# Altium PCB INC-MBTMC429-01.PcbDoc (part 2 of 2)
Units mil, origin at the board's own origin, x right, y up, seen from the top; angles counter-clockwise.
Board outline 6000 x 4000 mil, 2 copper layers (Top Layer, Bottom Layer); 198 components, 197 nets, 672 pads, 128 vias.
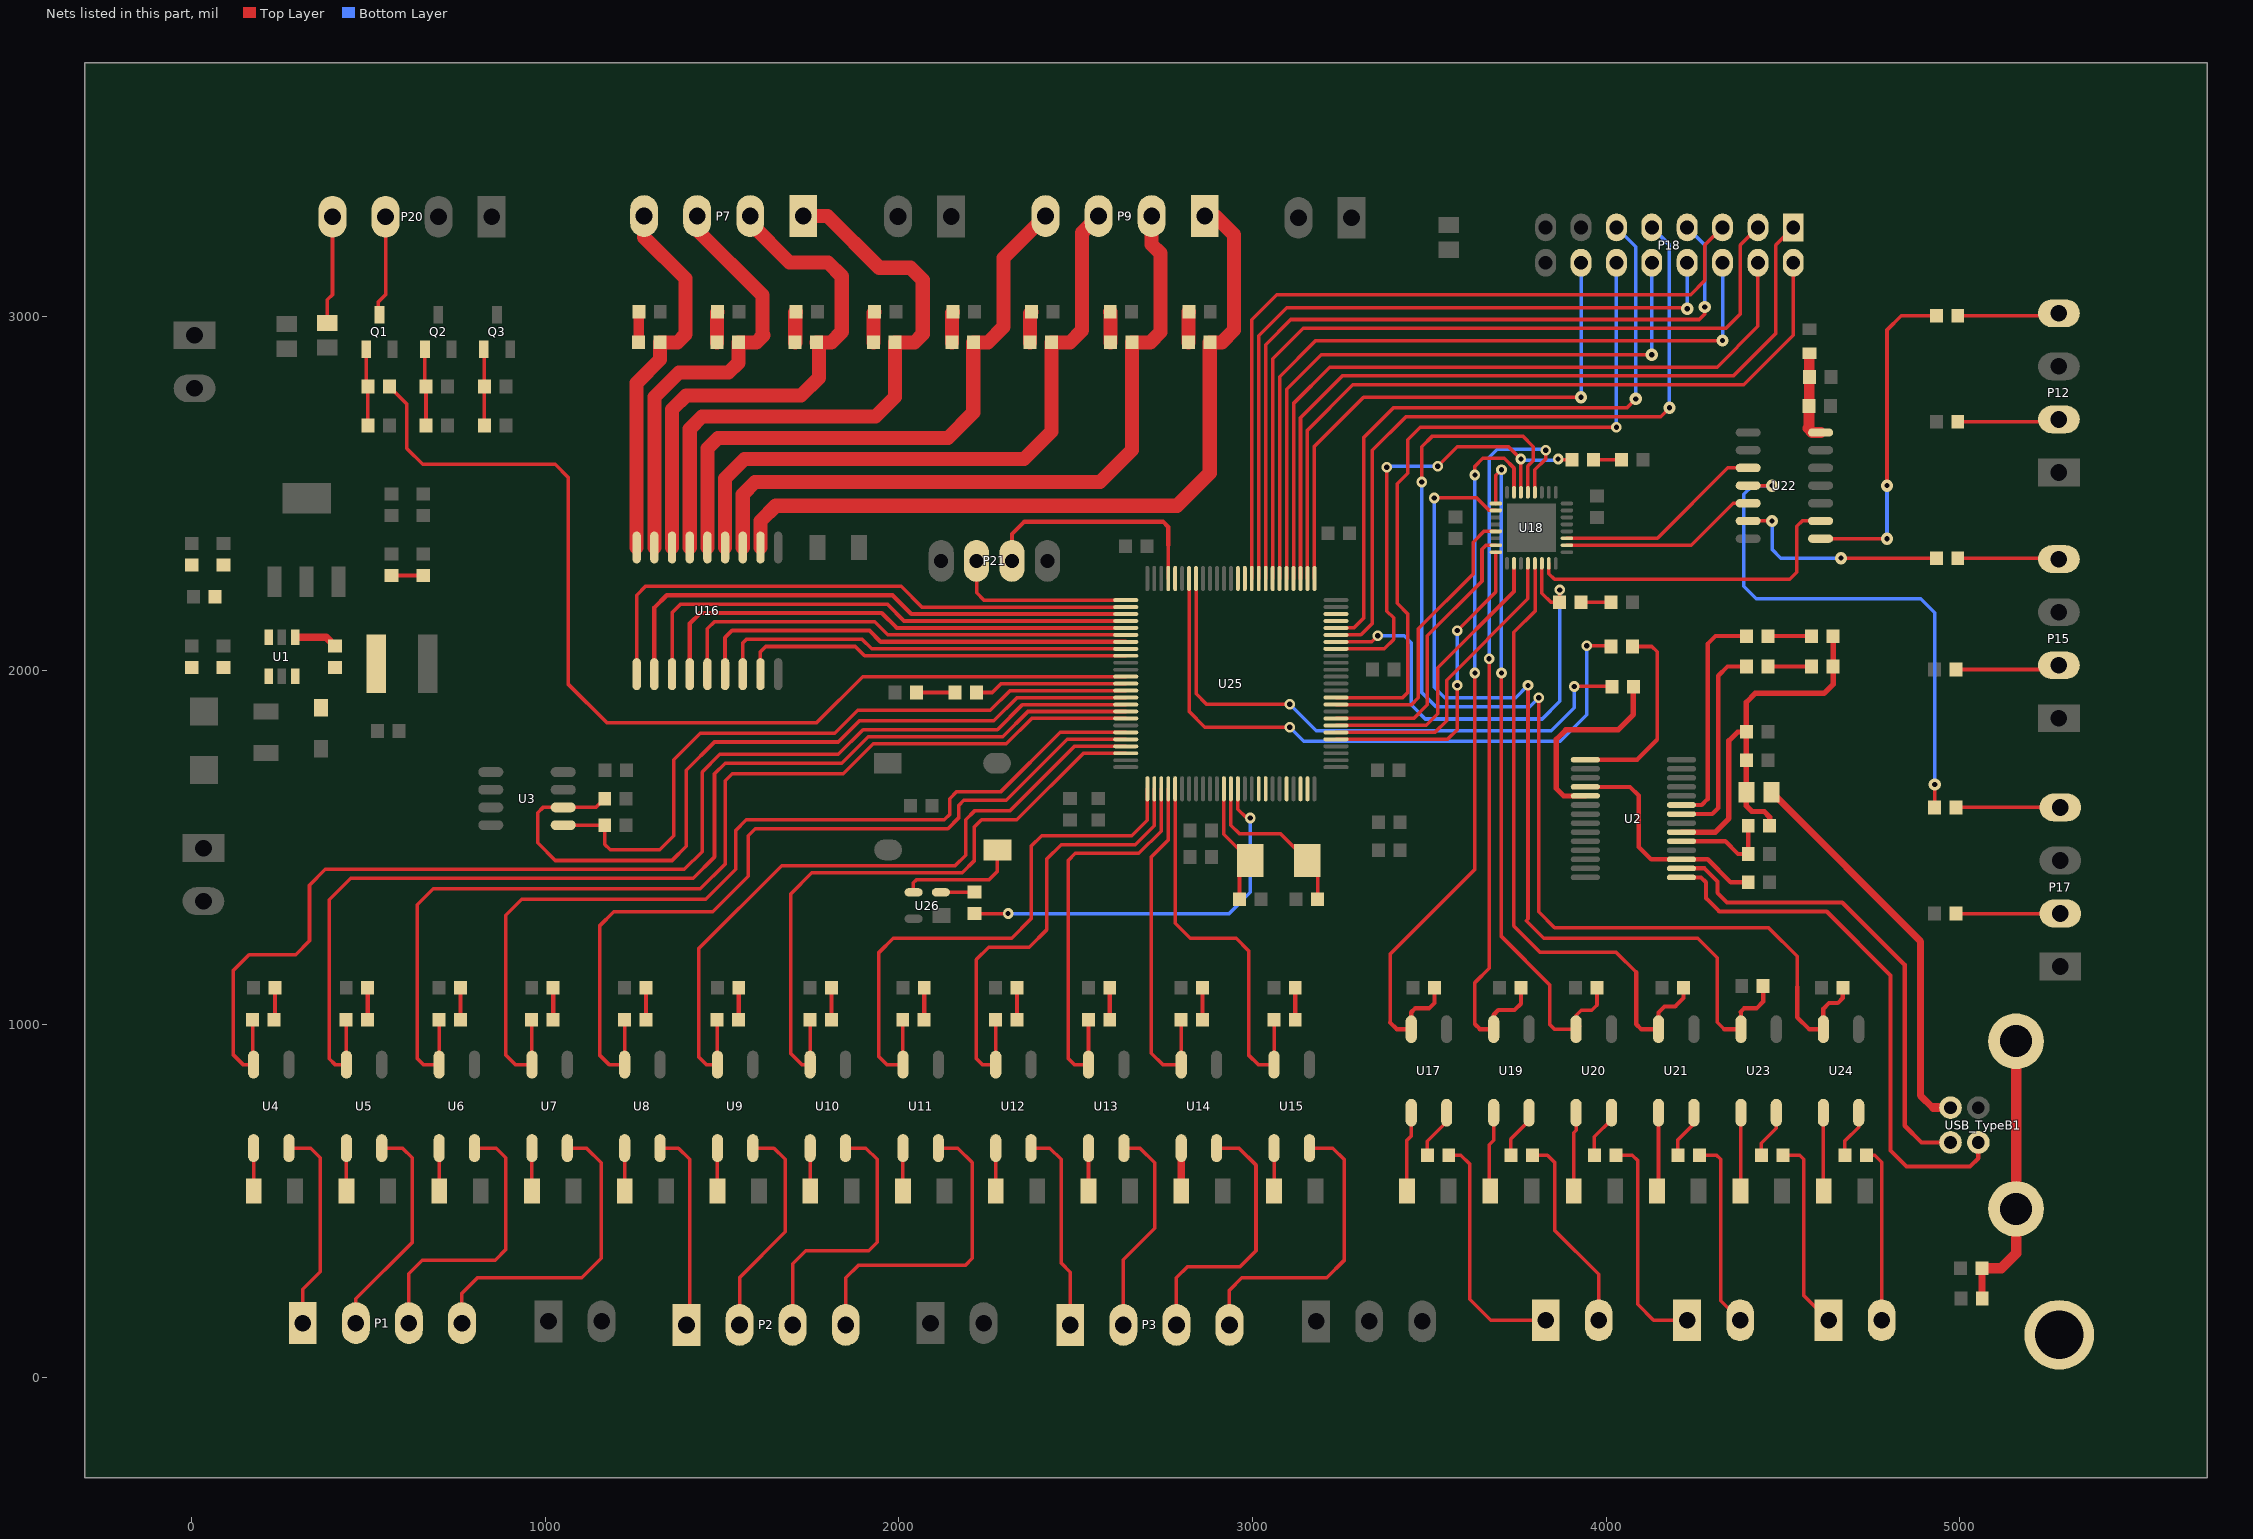
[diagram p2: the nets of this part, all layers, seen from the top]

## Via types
v1: diameter 30, hole 15, Top Layer to Bottom Layer, tented both sides, 91 vias
v2: diameter 35, hole 15, Top Layer to Bottom Layer, tented both sides, 17 vias
v3: diameter 50, hole 28, Top Layer to Bottom Layer, tented both sides, 16 vias
v4: diameter 47.24, hole 28, Top Layer to Bottom Layer, tented both sides, 2 vias
v5: diameter 30, hole 15, Top Layer to Bottom Layer, 1 vias
v6: diameter 50, hole 28, Top Layer to Bottom Layer, 1 vias

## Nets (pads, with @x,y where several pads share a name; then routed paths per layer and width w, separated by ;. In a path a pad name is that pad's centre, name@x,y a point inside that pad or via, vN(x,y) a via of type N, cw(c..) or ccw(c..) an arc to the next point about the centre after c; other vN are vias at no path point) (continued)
IIC_SCL: R12.1 U3.6 U25.90 | length 2291.5
  Top Layer w10: R12.1@1168.69,1638 1143.69,1613 U3.6@1051.36,1613 994,1613 979,1598 979,1513 1029,1463 1359,1463 1399,1503 1399,1718 1479,1798 1829,1798 1889,1858 2269,1858 2334.63,1923.63 U25.90@2641.76,1923.63
IIC_SDA: R13.1 U3.5 U25.89 | length 1963.9
  Top Layer w10: U3.5@1051.36,1563 R13.1@1168.69,1563 1168.69,1508.31 1184,1493 1324,1493 1364,1533 1364,1748 1439,1823 1819,1823 1884,1888 2259,1888 2314.32,1943.32 U25.89@2641.76,1943.32
IN1: D5.K U4.4 U25.91 | length 3493.7
  Top Layer w10: D5.K@173.37,1013 173.37,888.74 U4.4@176,886.11 145.89,886.11 119,913 119,1153 163,1197 295,1197 334,1236 334,1393 379,1438 1394,1438 1444,1488 1444,1713 1494,1763 1829,1763 1899,1833 2279,1833 2349.94,1903.94 U25.91@2641.76,1903.94
IN2: D7.K U5.4 U25.92 | length 3241.9
  Top Layer w10: D7.K@437.64,1013 438.27,1012.37 U5.4@438.27,886.11 405.89,886.11 390,902 390,1352 451,1413 1419,1413 1479,1473 1479,1708 1509,1738 1839,1738 1914,1813 2294,1813 2365.26,1884.26 U25.92@2641.76,1884.26
IN3: D8.K U6.4 U25.93 | length 2989.2
  Top Layer w10: D8.K@699.92,1013 700.55,1012.37 U6.4@700.55,886.11 655.89,886.11 639,903 639,1338 684,1383 1439,1383 1509,1453 1509,1688 1529,1708 1842.72,1708 1927.72,1793 2304,1793 2375.57,1864.57 U25.93@2641.76,1864.57
IN4: D9.K U7.4 U25.95 | length 2664.9
  Top Layer w10: D9.K@962.19,1013 962.82,1012.37 U7.4@962.82,886.11 915.89,886.11 889,913 889,1308 934,1353 1454,1353 1539,1438 1539,1548 1569,1578 2129,1578 2144,1593 2144,1638 2164,1658 2289,1658 2456.2,1825.2 U25.95@2641.76,1825.2
IN5: D10.K U8.4 U25.96 | length 2368.5
  Top Layer w10: D10.K@1224.46,1013 1225.09,1012.37 U8.4@1225.09,886.11 1180.89,886.11 1154,913 1154,1278 1194,1318 1474,1318 1574,1418 1574,1533 1594,1553 2139,1553 2169,1583 2169,1618 2184,1633 2304,1633 2476.52,1805.52 U25.96@2641.76,1805.52
IN6: D11.K U9.4 U25.97 | length 1998.2
  Top Layer w10: D11.K@1486.73,1013 1487.36,1012.37 U9.4@1487.36,886.11 1455.89,886.11 1434,908 1434,1213 1669,1448 2159,1448 2189,1478 2189,1578 2214,1603 2314,1603 2496.83,1785.83 U25.97@2641.76,1785.83
IN7: D12.K U10.4 U25.98 | length 1814.3
  Top Layer w10: D12.K@1749.01,1013 1749.64,1012.37 U10.4@1749.64,886.11 1725.89,886.11 1694,918 1694,1368 1754,1428 2179,1428 2214,1463 2214,1558 2234,1578 2334,1578 2522.15,1766.15 U25.98@2641.76,1766.15
IN8: D13.K U11.4 U25.1 | length 1621.8
  Top Layer w10: D13.K@2011.28,1013 2011.91,1012.37 U11.4@2011.91,886.11 1965.89,886.11 1944,908 1944,1203 1984,1243 2319,1243 2374,1298 2374,1503 2404,1533 2659,1533 2702.78,1576.78 U25.1@2702.78,1665.76
IN9: D14.K U12.4 U25.2 | length 1351
  Top Layer w10: D14.K@2273.55,1013 2274.18,1012.37 U12.4@2274.18,886.11 2235.89,886.11 2219,903 2219,1183 2254,1218 2369,1218 2419,1268 2419,1468 2459,1508 2669,1508 2722.46,1561.46 U25.2@2722.46,1665.76
IN10: D15.K U13.4 U25.3 | length 1168.8
  Top Layer w10: D15.K@2535.82,1013 2536.45,1012.37 U13.4@2536.45,886.11 2495.89,886.11 2479,903 2479,1463 2499,1483 2679,1483 2742.15,1546.15 U25.3@2742.15,1665.76
IN11: D16.K U14.4 U25.4 | length 992.7
  Top Layer w10: U25.4@2761.83,1665.76 2761.83,1520.83 2714,1473 2714,918 2745.89,886.11 U14.4@2798.73,886.11 2798.73,1012.37 D16.K@2798.1,1013
IN12: D17.K U15.4 U25.5 | length 1125.1
  Top Layer w10: U25.5@2781.52,1665.76 2781.52,1285.48 2824,1243 2954,1243 2989,1208 2989,913 3015.89,886.11 U15.4@3061,886.11 3061,1012.37 D17.K@3060.37,1013
INPUT1: P1.1 U4.2 | length 592.4
  Top Layer w10: U4.2@276,649.89 337.11,649.89 364,623 364,300 315,251 P1.1@315,155 P1.1@315,150
INPUT2: P1.2 U5.2 | length 635.7
  Top Layer w10: P1.2@465,150 P1.2@465,155 465,224 624,383 624,623 597.11,649.89 U5.2@538.27,649.89
INPUT3: P1.3 U6.2 | length 806.8
  Top Layer w10: P1.3@615,150 P1.3@615,155 615,295 653,333 859,333 889,363 889,623 862.11,649.89 U6.2@800.55,649.89
INPUT4: P1.4 U7.2 | length 907.5
  Top Layer w10: P1.4@765,150 P1.4@765,155 765,239 809,283 1104,283 1159,338 1159,608 1117.11,649.89 U7.2@1062.82,649.89
INPUT5: P2.1 U8.2 | length 568.8
  Top Layer w10: U8.2@1325.09,649.89 1377.11,649.89 1409,618 1409,159 P2.1@1400,150
INPUT6: P2.2 U9.2 | length 626.3
  Top Layer w10: P2.2@1550,150 1550,284 1679,413 1679,618 1647.11,649.89 U9.2@1587.36,649.89
INPUT7: P2.3 U10.2 | length 773.8
  Top Layer w10: P2.3@1700,150 1700,323 1737,360 1915,360 1939,384 1939,618 1907.11,649.89 U10.2@1849.64,649.89
INPUT8: P2.4 U11.2 | length 897.8
  Top Layer w10: P2.4@1850,150 1850,283 1885,318 2188,318 2208,338 2208,609 2167.11,649.89 U11.2@2111.91,649.89
INPUT9: P3.1 U12.2 | length 576.8
  Top Layer w10: U12.2@2374.18,649.89 2427.11,649.89 2459,618 2459,325 2485,299 P3.1@2485,150
INPUT10: P3.2 U13.2 | length 599.8
  Top Layer w10: P3.2@2635,150 2635,334 2724,423 2724,608 2682.11,649.89 U13.2@2636.45,649.89
INPUT11: P3.3 U14.2 | length 763
  Top Layer w10: P3.3@2785,150 2785,283 2817,315 2965,315 3010,360 3010,602 2962.11,649.89 U14.2@2898.73,649.89
INPUT12: P3.4 U15.2 | length 854
  Top Layer w10: P3.4@2935,150 2935,248 2970,283 3210,283 3259,332 3259,618 3227.11,649.89 U15.2@3161,649.89
INTOUT1: D33.K U18.14 U25.44 | length 1355.9
  Top Layer w10: U25.44@3236.24,2081.11 3337.11,2081.11 v1(3354,2098) ; U18.14@3818.13,2303.08 3818.13,2218.87 3844,2193 D33.K@3868.69,2193 3868.69,2227.69 v1(3869,2228)
  Bottom Layer w10: v1(3354,2098) 3429,2098 3449,2078 3449,1903 3489,1863 3819,1863 3869,1913 v1(3869,2228)
INTOUT2: P18.9 U25.45 | length 2026.5
  Top Layer w10: U25.45@3236.24,2100.8 3306.8,2100.8 3339,2133 3339,2623 3434,2718 4154,2718 v2(4179,2743)
  Bottom Layer w10: P18.9@4129,3253 4179,3203 v2(4179,2743)
LED1: R72.2 U25.88 | length 432.8
  Top Layer w10: R72.2@2219.32,1938 2264,1938 2289,1963 U25.88@2641.76,1963
MCU_RX: R11.1 U25.69 | length 1830.7
  Top Layer w10: U25.69@2820.89,2260.24 2820.89,1884.11 2865,1840 v1(3105,1840) ; v1(3945,2070) 4011.69,2070 R11.1@4013.69,2068
  Bottom Layer w10: v1(3105,1840) 3145,1800 3870,1800 3945,1875 v1(3945,2070)
MCU_TX: R9.1 U25.68 | length 1637.4
  Top Layer w10: U25.68@2840.57,2260.24 2840.57,1934.43 2870,1905 v1(3105,1905) ; v1(3910,1955) 4002.87,1955 4009.87,1948 R9.1@4016.37,1954.5
  Bottom Layer w10: v1(3105,1905) 3180,1830 3845,1830 3910,1895 v1(3910,1955)
NetC2_2: C2.2 R3.2 R4.1 U1.3
NetC3_1: C3.1 U1.1 | length 122.7
  Top Layer w20: U1.1@293.4,2094.12 381.51,2094.12 C3.1@406,2069.63
NetC3_2: C3.2 D2.2 L1.1 U1.6
NetC7_1: C7.1 pad.0 R6.1 USB_TypeB1.5 USB_TypeB1.6 | length 805.3
  Top Layer w20: C7.1@5062.63,310.53 5062.63,219.15 R6.1@5063.31,218.47
  Top Layer w30: C7.1@5062.63,310.53 5116.53,310.53 5159,353 USB_TypeB1.6@5159,478 USB_TypeB1.5@5159,952.02
NetC8_2: C8.2 C9.2 D4.A D6.A FB1.1 R10.2 U2.20 | length 1229.2
  Top Layer w15: U2.20@4212.83,1543.11 4308.61,1543.11 4347,1581.5 4347,1801.5 4372,1826.5 C8.2@4396.37,1826.5 ; R10.2@4462.32,1561.5 4462.31,1586.19 4447,1601.5 4412,1601.5 4396.37,1617.13 C9.2@4396.37,1746.5 C8.2@4396.37,1826.5 ; D4.A@4641.63,2097.5 D6.A@4641.63,2011.5 4641.63,1961.13 4616,1935.5 4421.37,1935.5 4396.37,1910.5 C8.2@4396.37,1826.5
NetC11_1: C11.1 R10.1 U2.19 | length 283.8
  Top Layer w12: U2.19@4212.83,1517.52 4337,1517.52 4373.02,1481.5 C11.1@4401.69,1481.5 R10.1@4401.69,1561.5
NetC16_1: C16.1 R77.2 SB1.1 U22.14 | length 255.9
  Top Layer w30: SB1.1@4575,2897.5 4574.68,2897.18 R77.2@4574.68,2830 4574.68,2749.31 C16.1@4573.37,2748 4573.37,2688.37 4570,2685 4582,2673 U22.14@4606.36,2673
NetD3_A: D3.A R5.2 | length 90.1
  Top Layer w12: R5.2@566,2268.68 655.68,2268.68 D3.A@656,2269
NetD4_K: D4.K R7.1 | length 124
  Top Layer w12: R7.1@4457,2097.5 D4.K@4581,2097.5
NetD5_A: D5.A R14.2 | length 91
  Top Layer w12: D5.A@234,1013 236.32,1015.32 R14.2@236.32,1103
NetD6_K: D6.K R8.2 | length 124
  Top Layer w12: R8.2@4457,2011.5 D6.K@4581,2011.5
NetD7_A: D7.A R15.2 | length 90.1
  Top Layer w12: D7.A@498.27,1013 498.56,1013.29 R15.2@498.56,1103
NetD8_A: D8.A R16.2 | length 90.1
  Top Layer w12: D8.A@760.55,1013 760.8,1013.26 R16.2@760.8,1103
NetD9_A: D9.A R17.2 | length 90.1
  Top Layer w12: D9.A@1022.82,1013 1023.05,1013.23 R17.2@1023.05,1103
NetD10_A: D10.A R18.2 | length 90.1
  Top Layer w12: D10.A@1285.09,1013 1285.29,1013.2 R18.2@1285.29,1103
NetD11_A: D11.A R19.2 | length 90.1
  Top Layer w12: D11.A@1547.36,1013 1547.54,1013.17 R19.2@1547.54,1103
NetD12_A: D12.A R20.2 | length 90.1
  Top Layer w12: D12.A@1809.64,1013 1809.78,1013.14 R20.2@1809.78,1103
NetD13_A: D13.A R21.2 | length 90
  Top Layer w12: D13.A@2071.91,1013 2072.02,1013.11 R21.2@2072.02,1103
NetD14_A: D14.A R22.2 | length 90
  Top Layer w12: D14.A@2334.18,1013 2334.27,1013.09 R22.2@2334.27,1103
NetD15_A: D15.A R23.2 | length 90
  Top Layer w12: D15.A@2596.45,1013 2596.51,1013.06 R23.2@2596.51,1103
NetD16_A: D16.A R24.2 | length 90
  Top Layer w12: D16.A@2858.76,1013.03 R24.2@2858.76,1103
NetD17_A: D17.A R25.2 | length 90
  Top Layer w12: D17.A@3121,1013 R25.2@3121,1103
NetD18_A: D18.A R38.1 | length 86.3
  Top Layer w30: D18.A@1264.37,2928 1264.37,3013.37 R38.1@1265,3014
NetD19_A: D19.A R39.1 | length 86.6
  Top Layer w40: D19.A@1485.8,2928 1485.8,3012.66 R39.1@1487.14,3014
NetD20_A: D20.A R40.1 | length 86.9
  Top Layer w40: D20.A@1707.23,2928 1707.23,3011.94 R40.1@1709.29,3014
NetD21_A: D21.A R41.1 | length 87.1
  Top Layer w40: D21.A@1928.66,2928 1928.66,3011.23 R41.1@1931.43,3014
NetD22_A: D22.A R42.1 | length 87.4
  Top Layer w40: D22.A@2150.08,2928 2150.08,3010.51 R42.1@2153.57,3014
NetD23_A: D23.A R43.1 | length 87.7
  Top Layer w40: D23.A@2371.51,2928 2371.51,3009.8 R43.1@2375.71,3014
NetD24_A: D24.A R44.1 | length 86.3
  Top Layer w40: R44.1@2597.86,3014 2598.68,3013.17 D24.A@2598.68,2928
NetD25_A: D25.A R45.1 | length 86.5
  Top Layer w40: D25.A@2818.68,2928 2818.68,3012.69 R45.1@2820,3014
NetD26_A: D26.A U17.2 | length 142.5
  Top Layer w10: D26.A@3494.37,630 3494.37,669.37 3549,724 U17.2@3549,749.89
NetD27_A: D27.A U19.2 | length 141.2
  Top Layer w10: D27.A@3730.5,630 3730.5,675.5 3782,727 U19.2@3782,749.89
NetD28_A: D28.A U20.2 | length 139.9
  Top Layer w10: D28.A@3966.62,630 3966.62,681.62 4015,730 U20.2@4015,749.89
NetD29_A: D29.A U21.2 | length 138.6
  Top Layer w10: D29.A@4202.75,630 4202.75,672.75 4248,718 U21.2@4248,749.89
NetD30_A: D30.A U23.2 | length 137.3
  Top Layer w10: D30.A@4438.87,630 4438.87,663.87 4481,706 U23.2@4481,749.89
NetD31_A: D31.A U24.2 | length 136
  Top Layer w10: D31.A@4675,630 4675,670 4714,709 U24.2@4714,749.89
NetD32_A: D32.A R58.1 | length 78.4
  Top Layer w10: R58.1@3964.63,2596 D32.A@4043,2596
NetD33_A: D33.A R63.1 | length 84.7
  Top Layer w10: D33.A@3929.32,2193 R63.1@4014,2193
NetD34_K: D34.K R72.1 | length 109.1
  Top Layer w10: D34.K@2049.63,1938 R72.1@2158.69,1938
NetP12_2: P12.2 R60.2 | length 292.1
  Top Layer w10: R60.2@4994,2703 5279,2703 P12.2@5284,2708
NetP12_4: P12.4 R59.2 | length 292.1
  Top Layer w10: R59.2@4994,3003 5279,3003 P12.4@5284,3008
NetP15_2: P15.2 R62.2 | length 297.8
  Top Layer w10: R62.2@4989.32,2003 5276.5,2003 P15.2@5284,2010.5
NetP15_4: P15.4 R61.2 | length 293.1
  Top Layer w10: R61.2@4994,2318 5276.5,2318 P15.4@5284,2310.5
NetP17_2: P17.2 R65.2 | length 294.7
  Top Layer w10: R65.2@4989.32,1313 P17.2@5284,1313
NetP17_4: P17.4 R64.2 | length 294.7
  Top Layer w10: R64.2@4989.32,1613 P17.4@5284,1613
NetP20_4: P20.4 R68.2 | length 306.1
  Top Layer w10: R68.2@384,2983.08 384,3048 399,3063 P20.4@399,3283
NetQ1_1: Q1.1 R67.1 R73.2 | length 217
  Top Layer w10: Q1.1@494.2,2908 494.2,2807.8 R67.1@499,2803 R73.2@499,2693
NetQ2_1: Q2.1 R69.1 R74.2 | length 216.6
  Top Layer w10: Q2.1@660.4,2908 660.4,2806.44 R69.1@663.84,2803 663.37,2802.53 R74.2@663.37,2693
NetQ3_1: Q3.1 R70.1 R75.2 | length 216
  Top Layer w10: Q3.1@826.6,2908 828.68,2905.91 R70.1@828.68,2803 828.37,2802.68 R75.2@828.37,2693
NetR1_1: R1.1 R2.1 U1.4
NetR7_2: R7.2 U2.23 | length 638.5
  Top Layer w12: U2.23@4212.83,1619.89 4270.39,1619.89 4287,1636.5 4287,2075.5 4309,2097.5 R7.2@4396.37,2097.5
NetR8_1: R8.1 U2.22 | length 575.4
  Top Layer w12: U2.22@4212.83,1594.3 4299.8,1594.3 4317,1611.5 4317,1985.5 4343,2011.5 R8.1@4396.37,2011.5
NetR9_2: R9.2 U2.5 | length 555.9
  Top Layer w15: U2.5@3941.17,1645.48 3880.02,1645.48 3859,1666.5 3859,1805.5 3886,1832.5 4034,1832.5 4077,1875.5 R9.2@4077,1954.5
NetR11_2: R11.2 U2.1 | length 550.9
  Top Layer w10: R11.2@4074.32,2068 4129,2068 4144,2053 4144,1804.18
  Top Layer w12: U2.1@3941.17,1747.84 4087.66,1747.84 4144,1804.18
NetR26_2: R26.2 U4.1 | length 121.9
  Top Layer w10: R26.2@176,528 U4.1@176,649.89
NetR27_2: R27.2 U5.1 | length 121.9
  Top Layer w10: R27.2@438.27,528 U5.1@438.27,649.89
NetR28_2: R28.2 U6.1 | length 121.9
  Top Layer w10: R28.2@700.55,528 U6.1@700.55,649.89
NetR29_2: R29.2 U7.1 | length 121.9
  Top Layer w10: R29.2@962.82,528 U7.1@962.82,649.89
NetR30_2: R30.2 U8.1 | length 121.9
  Top Layer w10: R30.2@1225.09,528 U8.1@1225.09,649.89
NetR31_2: R31.2 U9.1 | length 121.9
  Top Layer w10: R31.2@1487.36,528 U9.1@1487.36,649.89
NetR32_2: R32.2 U10.1 | length 121.9
  Top Layer w10: R32.2@1749.64,528 U10.1@1749.64,649.89
NetR33_2: R33.2 U11.1 | length 121.9
  Top Layer w10: R33.2@2011.91,528 U11.1@2011.91,649.89
NetR34_2: R34.2 U12.1 | length 121.9
  Top Layer w10: R34.2@2274.18,528 U12.1@2274.18,649.89
NetR35_2: R35.2 U13.1 | length 121.9
  Top Layer w10: R35.2@2536.45,528 U13.1@2536.45,649.89
NetR36_2: R36.2 U14.1 | length 121.9
  Top Layer w20: R36.2@2798.73,528 U14.1@2798.73,649.89
NetR37_2: R37.2 U15.1 | length 121.9
  Top Layer w10: R37.2@3061,528 U15.1@3061,649.89
NetR46_2: R46.2 U17.1 | length 279.3
  Top Layer w10: R46.2@3449,505.28 3449,540.28 R46.2@3436.72,528 3436.72,671.72 3449,684 U17.1@3449,749.89
NetR47_2: R47.2 U19.1 | length 228.7
  Top Layer w10: R47.2@3672.45,528 3669,531.45 3669,659 3682,672 U19.1@3682,749.89
NetR48_2: R48.2 U20.1 | length 269.4
  Top Layer w10: R48.2@3915,499.83 3915,534.83 R48.2@3908.17,528 3908.17,693.17 3915,700 U20.1@3915,749.89
NetR49_2: R49.2 U21.1 | length 217.8
  Top Layer w10: R49.2@4148,532.11 U21.1@4148,749.89
NetR50_2: R50.2 U23.1 | length 222.5
  Top Layer w10: R50.2@4379.62,528 4381,529.38 U23.1@4381,749.89
NetR51_2: R51.2 U24.1 | length 222.4
  Top Layer w10: U24.1@4614,749.89 4614,529.34 R51.2@4615.34,528
NetR66_2: R66.2 U26.2 | length 95.1
  Top Layer w10: U26.2@2119,1373 2213.68,1373 R66.2@2214,1373.32
NetS1_1: S1.1 U26.3 | length 339
  Top Layer w10: U26.3@2041.83,1373 2041,1373.83 2041,1400 2049,1408 2254,1408 2279,1433 S1.1@2279,1493
OSC_IN: C22.2 U25.12 Y1.2 | length 356.4
  Top Layer w10: U25.12@2919.31,1665.76 2919.31,1537.68 Y1.2@2994,1463 2963.37,1432.37 C22.2@2963.37,1353
OSC_OUT: C23.2 U25.13 Y1.1 | length 482.4
  Top Layer w10: U25.13@2939,1665.76 2939,1563 2964,1538 3080.42,1538 Y1.1@3155.42,1463 3184,1434.42 C23.2@3184,1353
OUT1: U16.1 U25.77 | length 1640.6
  Top Layer w10: U16.1@1259,1989.73 1259,2213 1284,2238 2007,2238 2065.46,2179.54 U25.77@2641.76,2179.54
OUT2: U16.2 U25.78 | length 1557.5
  Top Layer w12: U16.2@1309,1989.73 1309,2178 1344,2213 1982,2213 2035.15,2159.85 U25.78@2641.76,2159.85
OUT3: U16.3 U25.79 | length 1486.2
  Top Layer w10: U16.3@1359,1989.73 1359,2163 1384,2188 1967,2188 2014.83,2140.17 U25.79@2641.76,2140.17
OUT4: U16.4 U25.80 | length 1406.1
  Top Layer w12: U16.4@1409,1989.73 1409,2133 1439,2163 1952,2163 1994.52,2120.48 U25.80@2641.76,2120.48
OUT5: U16.5 U25.81 | length 1334.7
  Top Layer w10: U16.5@1459,1989.73 1459,2118 1479,2138 1932,2138 1969.2,2100.8 U25.81@2641.76,2100.8
OUT6: U16.6 U25.82 | length 1257.5
  Top Layer w12: U16.6@1509,1989.73 1509,2093 1529,2113 1917,2113 1948.89,2081.11 U25.82@2641.76,2081.11
OUT7: U16.7 U25.83 | length 1186.2
  Top Layer w10: U16.7@1559,1989.73 1559,2078 1569,2088 1897,2088 1923.57,2061.43 U25.83@2641.76,2061.43
OUT8: U16.8 U25.84 | length 1113.1
  Top Layer w10: U16.8@1609,1989.73 1609,2053 1624,2068 1877,2068 1903.26,2041.74 U25.84@2641.76,2041.74
OUTPUT1: D18.K P7.4 U16.18 | length 1071.3
  Top Layer w40: U16.18@1259,2348 1259,2813 1325,2879 D18.K@1325,2928 1374,2928 1397,2951 1397,3108 1280,3225 P7.4@1280,3285
OUTPUT2: D19.K P7.3 U16.17 | length 1253.7
  Top Layer w40: U16.17@1309,2348 1309,2773 1379,2843 1519,2843 1546.43,2870.43 D19.K@1546.43,2928 1597,2928 1617,2948 1615,2950 1615,3061 1430,3246 P7.3@1430,3285
OUTPUT3: D20.K P7.2 U16.16 | length 1526.5
  Top Layer w40: U16.16@1359,2348 1359,2548 1359,2738 1399,2778 1724,2778 1774,2828 1774,2921.86 D20.K@1767.86,2928 1809,2928 1839,2958 1839,3115 1800,3154 1691,3154 1580,3265 P7.2@1580,3285
OUTPUT4: D21.K P7.1 U16.15 | length 1761
  Top Layer w40: U16.15@1409,2348 1409,2618 1409,2683 1444,2718 1934,2718 1989.29,2773.29 D21.K@1989.29,2928 2044,2928 2068,2952 2068,3104 2033,3139 1945,3139 1799,3285 P7.1@1730,3285
OUTPUT5: D22.K P9.4 U16.14 | length 1737.9
  Top Layer w40: U16.14@1459,2348 1459,2628 1489,2658 2139,2658 2210.71,2729.71 D22.K@2210.71,2928 2252,2928 2296,2972 2296,3166 P9.4@2415,3285
OUTPUT6: D23.K P9.3 U16.13 | length 1867.6
  Top Layer w40: U16.13@1509,2348 1509,2543 1564,2598 2354,2598 2432.14,2676.14 D23.K@2432.14,2928 2484,2928 2518,2962 2518,3238 P9.3@2565,3285
OUTPUT7: D24.K P9.2 U16.12 | length 2038
  Top Layer w40: U16.12@1559,2348 1559,2498 1594,2533 2569,2533 2659.31,2623.31 D24.K@2659.31,2928 2711,2928 2740,2957 2740,3180 2715,3205 P9.2@2715,3285
OUTPUT8: D25.K P9.1 U16.11 | length 2196.8
  Top Layer w40: U16.11@1609,2348 1609,2423 1652,2466 2787,2466 2879.31,2558.31 D25.K@2879.31,2928 2913,2928 2948,2963 2948,3232 P9.1@2896,3284
PA0: U25.23
PA1: U25.24
PA12: U25.71
PB10: U25.47
PB11: U25.48
PC2: U25.17
PC3: U25.18
POSCMP1: R58.2 U18.30 U25.43 | length 1331.5
  Top Layer w10: U25.43@3236.24,2061.43 3372.43,2061.43 3399,2088 3399,2149 3380,2168 v1(3380,2575) ; v1(3524,2578) 3579,2633 3724,2633 v1(3759,2598) 3754,2593 3759.08,2587.92 U18.30@3759.08,2503.87 ; v1(3864,2598) 3866,2596 R58.2@3904,2596
  Bottom Layer w10: v1(3380,2575) 3383,2578 v1(3524,2578) ; v1(3759,2598) 3762,2595 v1@3864,2595
POSCMP2: P18.11 U25.46 | length 1927.5
  Top Layer w10: U25.46@3236.24,2120.48 3286.48,2120.48 3314,2148 3314,2658 3398.5,2742.5 4058.5,2742.5 v2(4084,2768)
  Bottom Layer w10: P18.11@4029,3253 4084,3198 v2(4084,2768) v2@4084,2763
PUL1+: R59.1 U22.8 | length 933.6
  Top Layer w10: U22.8@4606.36,2373 v2(4794,2373) ; v2(4794,2523) 4794,2963 4834,3003 R59.1@4933.37,3003
  Bottom Layer w10: v2(4794,2373) v2(4794,2523)
PUL2+: R61.1 U22.6 | length 622.1
  Top Layer w10: U22.6@4401.64,2423 4404,2423 v2(4469,2423) ; v2(4664,2318) R61.1@4933.37,2318
  Bottom Layer w10: v2(4469,2423) 4469,2343 4494,2318 v2(4664,2318)
PUL3+: R64.1 U22.4 | length 1538.9
  Top Layer w10: U22.4@4401.64,2523 v2(4469,2523) ; R64.1@4928.69,1613 4929,1613.31 v2(4929,1678)
  Bottom Layer w10: v2(4469,2523) 4414,2523 4389,2498 4389,2238 4424,2203 4889,2203 4929,2163 v2(4929,1678)
RED: R67.2 U25.87 | length 2945.6
  Top Layer w10: R67.2@559.63,2803 609,2753.63 609,2628 654,2583 1029,2583 1065,2547 1065,1962 1174,1853 1768,1853 1897.68,1982.68 U25.87@2641.76,1982.68
Red_LED: P20.3 Q1.3 | length 285.9
  Top Layer w10: Q1.3@531.6,3006.43 529,3009.02 529,3043 549,3063 P20.3@549,3283
REF1: R52.2 U17.4 U18.31 | length 2106.8
  Top Layer w10: 3389,1005 3389,1198 3629,1438 v1(3629,1993) ; v1(3629,2553) 3629,2578 3651,2600 3712,2600 3739.39,2572.61 U18.31@3739.39,2503.87
  Top Layer w12: 3389,1005 3407.89,986.11 U17.4@3449,986.11 3449,1034 3460,1045 3499.32,1045 3514.32,1060 R52.2@3514.32,1103
  Bottom Layer w10: v1(3629,1993) v1(3629,2553)
REF2: R54.2 U18.1 U20.4 | length 1980
  Top Layer w10: U18.1@3688.21,2472.37 3688.21,2552.21 v1(3704,2568) ; v1(3704,1993) 3704,1248 3840,1112 3840,1000 3853.89,986.11 U20.4@3915,986.11 3915,1025 3930,1040 3959.32,1040 3974.32,1055 ; U20.4@3915,985 U20.4@3925,995
  Top Layer w12: 3974.32,1055 R54.2@3974.32,1103
  Bottom Layer w10: v1(3704,1993) v1(3704,2568)
REF3: R56.2 U18.2 U23.4 | length 2692.9
  Top Layer w10: v1(3514,2488) 3634,2488 3669.31,2452.68 U18.2@3688.21,2452.68 ; v1(3779,1958) 3779,1298 3774,1293 3824,1243 4259,1243 4314,1188 4314,1006 4333.89,986.11
  Top Layer w12: 4333.89,986.11 U23.4@4381,986.11 4381,1034 4380,1035 4390,1045 4425,1045 4444,1064 R56.2@4444,1108
  Bottom Layer w10: v1(3514,2488) 3514,1953 3544,1923 3744,1923 v1(3779,1958)
REF_L1: D26.K P11.1 | length 691.2
  Top Layer w10: D26.K@3555,630 3589,630 3614,605 3614,223 3674,163 P11.1@3829,163
REF_L2: D28.K P13.1 | length 633.6
  Top Layer w10: D28.K@4027.25,630 4074,630 4089,615 4089,208 4134,163 P13.1@4229,163
REF_L3: D30.K P14.1 | length 548.5
  Top Layer w10: D30.K@4499.5,630 4547,630 4559,618 4559,233 P14.1@4629,163
REF_R1: D27.K P11.2 | length 569.9
  Top Layer w10: D27.K@3791.13,630 3834,630 3854,610 3854,418 3979,293 P11.2@3979,163
REF_R2: D29.K P13.2 | length 543.4
  Top Layer w10: D29.K@4263.38,630 4312,630 4324,618 4324,218 P13.2@4379,163
REF_R3: D31.K P14.2 | length 498.7
  Top Layer w10: D31.K@4735.63,630 4759,630 4779,610 P14.2@4779,163
REFR1: R53.2 U18.28 U19.4 | length 2160.2
  Top Layer w10: 3629,1000 3629,1118 3669,1158 v1(3669,2033) ; U18.28@3798.45,2503.87 3798.45,2567.45 3829,2598 v1(3829,2623)
  Top Layer w12: 3629,1000 3642.89,986.11 U19.4@3682,986.11 3682,1027 3695,1040 3741,1040 3759,1058 R53.2@3759,1103 ; U19.4@3682,981 U19.4@3684.56,983.56
  Bottom Layer w10: v1(3669,2033) 3669,2603 3692,2626 3826,2626 v1(3829,2623)
REFR2: R55.2 U18.13 U21.4 | length 1830
  Top Layer w10: U18.13@3798.45,2303.08 3799,2302.53 3799,2168 3739,2108 3739,1278 3814,1203 4029,1203 4085,1147
  Top Layer w12: 4085,1147 4085,1000 4098.89,986.11 U21.4@4148,986.11 4148,1033 4165,1050 4195,1050 4219,1074 R55.2@4219,1103
REFR3: R57.2 U18.29 U24.4 | length 3345.3
  Top Layer w10: v1(3479,2533) 3479,2633 3509,2663 3764,2663 3794,2633 3794,2593.4 3778.76,2578.17 U18.29@3778.76,2503.87 ; v1(3809,1923) 3809,1318 3854,1273 4459,1273 4540,1192 4540,1105 ; U24.4@4614,984 U24.4@4625,995
  Top Layer w12: 4540,1105 4540,1020 4573.89,986.11 U24.4@4614,986.11 4614,1044 4630,1060 4655,1060 4669,1074 R57.2@4669,1103
  Bottom Layer w10: v1(3479,2533) 3479,1938 3519,1898 3784,1898 v1(3809,1923)
RST: R66.1 U25.14 | length 1118.2
  Top Layer w10: R66.1@2214,1312.69 2308.69,1312.69 v1(2309,1313) ; U25.14@2958.69,1665.76 2958.69,1608.32 2984,1583 v1(2994,1583)
  Bottom Layer w10: v1(2309,1313) 2934,1313 2994,1373 v1(2994,1583)
SPI1_CS: U18.7 U25.33 | length 821.8
  Top Layer w10: U25.33@3236.24,1864.57 3455.57,1864.57 3494,1903 3494,2098 3649,2253 3649,2343 3660.26,2354.26 U18.7@3688.21,2354.26
SPI1_MISO: U18.12 U25.31 | length 866.6
  Top Layer w10: U25.31@3236.24,1825.2 3516.2,1825.2 3549,1858 3549,1973 3778.76,2202.76 U18.12@3778.76,2303.08
SPI1_MOSI: U18.10 U25.32 | length 815.8
  Top Layer w10: U25.32@3236.24,1844.89 3490.89,1844.89 3524,1878 3524,2008 3739.39,2223.39 U18.10@3739.39,2303.08
SPI1_SCK: U18.8 U25.30 | length 901
  Top Layer w10: U25.30@3236.24,1805.52 3551.52,1805.52 3579,1833 v1(3579,1958) ; v1(3579,2113) 3688.21,2222.21 U18.8@3688.21,2334.57
  Bottom Layer w10: v1(3579,1958) v1(3579,2113)
SPI2_CS: P18.14 U25.51 | length 1577.7
  Top Layer w10: U25.51@3175.22,2260.24 3175.22,2634.22 3314,2773 v2(3929,2773)
  Bottom Layer w10: v2(3929,2773) 3929,3123 3944,3138 P18.14@3929,3153
SPI2_MISO: P18.1 U25.53 | length 2217.1
  Top Layer w10: U25.53@3135.85,2260.24 3135.85,2714.85 3254,2833 4359,2833 4479,2953 4479,3203 P18.1@4529,3253
SPI2_MOSI: P18.4 U25.54 | length 2078
  Top Layer w10: U25.54@3116.17,2260.24 3116.17,2755.17 3219,2858 4314,2858 4429,2973 P18.4@4429,3153
SPI2_SCK: P18.2 U25.52 | length 2109
  Top Layer w10: U25.52@3155.54,2260.24 3155.54,2679.54 3284,2808 4389,2808 4529,2948 P18.2@4529,3153
Step1: U18.15 U22.9 | length 948.6
  Top Layer w10: U18.15@3837.82,2303.08 3837.82,2274.18 3854,2258 4519,2258 4539,2278 4539,2408 4554,2423 U22.9@4606.36,2423
Step2: U18.18 U22.5 | length 561.8
  Top Layer w10: U18.18@3889,2354.26 4240.26,2354.26 4359,2473 U22.5@4401.64,2473
Step3: U18.19 U22.3 | length 595.1
  Top Layer w10: U18.19@3889,2373.94 4144.94,2373.94 4344,2573 U22.3@4401.64,2573
SWCLK: P21.2 U25.76 | length 520.4
  Top Layer w10: P21.2@2220,2310 2220,2220 2240.78,2199.22 U25.76@2641.76,2199.22
SWDIO: P21.3 U25.72 | length 684.4
  Top Layer w10: U25.72@2761.83,2260.24 2761.83,2355.17
  Top Layer w12: P21.3@2320,2310 2320,2386 2355,2421 2747,2421 2761.83,2406.17 2761.83,2355.17
TIM4_CH3: U25.61
TIM4_CH4: U25.62
TMC262_CS1: P18.10 U25.55 | length 1868.1
  Top Layer w10: U25.55@3096.48,2260.24 3096.48,2795.48 3194,2893 v2(4129,2893)
  Bottom Layer w10: v2(4129,2893) P18.10@4129,3153
TMC262_CS2: P18.6 U25.56 | length 2085.1
  Top Layer w10: U25.56@3076.8,2260.24 3076.8,2830.8 3179,2933 v2(4329,2933)
  Bottom Layer w10: v2(4329,2933) P18.6@4329,3153
TMC262_CS3: P18.3 U25.57 | length 2261
  Top Layer w10: U25.57@3057.11,2260.24 3057.11,2881.11 3144,2968 4339,2968 4379,3008 4379,3203 P18.3@4429,3253
TMC262_EN1: P18.7 U25.58 | length 2204.3
  Top Layer w10: U25.58@3037.43,2260.24 3037.43,2921.43 3108.5,2992.5 4263.5,2992.5 4279,3008 v2(4279,3028)
  Bottom Layer w10: P18.7@4229,3253 4279,3203 v2(4279,3028)
TMC262_EN2: P18.8 U25.59 | length 2061.4
  Top Layer w10: U25.59@3017.74,2260.24 3017.74,2946.74 3096.48,3025.48 4226.52,3025.48 v2(4229,3023)
  Bottom Layer w10: v2(4229,3023) P18.8@4229,3153
TMC262_EN3: P18.5 U25.60 | length 2229.4
  Top Layer w10: U25.60@2998.06,2260.24 2998.06,2992.06 3069,3063 4239,3063 4279,3103 4279,3203 P18.5@4329,3253
TMC429_CLK1: U18.5 U25.35 | length 821.8
  Top Layer w10: U25.35@3236.24,1903.94 3449.94,1903.94 3469,1923 3469,2118 3624,2273 3624,2363 3654.63,2393.63 U18.5@3688.21,2393.63
TMC429_CLK2: P18.12 U25.36 | length 2018.1
  Top Layer w10: U25.36@3236.24,1923.63 3424.63,1923.63 3439,1938 3439,2160 3409,2190 3409,2528 3439,2558 3439,2653 3474,2688 v1(4029,2688)
  Bottom Layer w10: v1(4029,2688) P18.12@4029,3153
USB_D+: U2.15 USB_TypeB1.3 | length 1548.4
  Top Layer w12: U2.15@4212.83,1415.16 4268.34,1415.16 4282,1401.5 4282,1356.5 4320,1318.5 4623.5,1318.5 4804,1138 4804,643 4849,598 5029,598 5052.31,621.31 USB_TypeB1.3@5052.31,665.8
USB_D-: U2.16 USB_TypeB1.2 | length 1367
  Top Layer w12: U2.16@4212.83,1440.75 4277.75,1440.75 4315,1403.5 4315,1371.5 4342,1344.5 4667.5,1344.5 4844,1168 4844,713 4891.2,665.8 USB_TypeB1.2@4973.57,665.8
USB_VBUS: FB1.2 USB_TypeB1.1 | length 1132.9
  Top Layer w20: FB1.2@4467.04,1656.5 4889,1234.54 4889,798 4924,763 4925.22,764.22
  Top Layer w25: 4925.22,764.22 USB_TypeB1.1@4973.57,764.22
VCCIO: C10.1 U2.4 U2.17 | length 657.1
  Top Layer w12: U2.4@3941.17,1671.07 4067.43,1671.07 4092,1646.5 4092,1501.5 4127.16,1466.34 U2.17@4212.83,1466.34 4287.16,1466.34 4352,1401.5 C10.1@4401.69,1401.5
Vref_2.5V: U25.21
pads on no net: U2.2 U2.3 U2.6 U2.8 U2.9 U2.10 U2.11 U2.12 U2.13 U2.14 U2.24 U2.27 U2.28 U18.9 U18.11 U18.16 U18.24 U18.26 U18.32 U25.6 U25.7 U25.8 U25.9 U25.25 U25.26 U25.29 U25.34 U25.38 U25.39 U25.40 U25.41 U25.42 U25.63 U25.64 U25.65 U25.66 U25.67 U25.70 U25.73

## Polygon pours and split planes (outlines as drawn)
GND on Bottom Layer "Top Layer-No Net" (solid, remove dead copper, pour order 4): -28,3047 17,3047 381,3411 4858,3411 5354,2915 5354,510 4902,58 321,58 -34,413 -31,416 -31,3043 -28,3046
GND on Top Layer "Top Layer-No Net" (solid, remove dead copper, pour order 2): -26,3042 13,3042 382,3411 4857,3411 5353,2915 5353,508 4903,58 333,58 -30,421 -30,3038

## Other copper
Top Layer:
  rectangle net GND: 4631,2700 4684,2761
  rectangle net NetC7_1: 5072,101 5329,317
  rectangle net +3.3V: 3880,2410 3902,2434
  rectangle net DCin: -36,1448 125,1761
  rectangle net +24V: 1652,2327 1781,2372
  rectangle net +24V: -65,1873 149,1935
  rectangle net +3.3V: 311,2244 341,2479
  rectangle net +5V: -19,2339 175,2391
  rectangle net NetC8_2: 4380,1635.5 4414,1841.5
  region net NetC7_1: 5119,373 5089,343 5059,343 5059,328 5049,318 5054,313 5054,223 5064,223 5079,208 5099,208 5229,313 5229,958 5189,998 5134,998 5119,983
  region net +24V: 267,2001 246,2001 244,1999 244,1952 226,1934 -35,1934 -39,1938 -39,2043 -29,2053 15,2053 21,2059 21,2083 15,2089 -41,2089 -59,2071 -59,1901 -20,1862 251,1862 267,1878
  region net NetR1_1: 208,2025 230,2003 230,1970 223,1963 -7,1963 -19,1975 -19,2022 -15,2026 -14,2025
  region net GND: 160,1811 413,1811 468,1866 524,1866 539,1851 539,1726 503,1690 214,1690 161,1743 161,1810
  region net +5V: 616,1919 611,1919 566,1874 566,1729 601,1694 676,1694 696,1714 696,2089 681,2104 616,2104
  region net NetC3_2: 361,2004 381,2024 471,2024 486,2039 486,2089 496,2099 556,2099 566,2089 566,1949 556,1939 421,1939 406,1924 406,1889 391,1874 301,1874 286,1889 286,2004
  region net NetC2_2: 231,2079 231,2097 184,2144 121,2207 121,2304 111,2314 -14,2314 -19,2309 -19,2289 -4,2274 41,2274 51,2264 51,2134 61,2124 166,2124 206,2084 211,2079
  region net +3.3V: 671,2529 686,2514 686,2494 676,2484 516,2484 491,2459 491,2379 501,2369 511,2369 591,2369 601,2359 601,2324 586,2309 491,2309 446,2354 446,2414 416,2444 276,2444 261,2459 261,2524 266,2529
Bottom Layer:
  rectangle net +5V: 624,1728 664,1843
  rectangle net +5V: 353,2816 421,2960
  rectangle net +3.3V: 1031,1100 1173,1226
  rectangle net +3.3V: 345,1135 4626,1168
  rectangle net +24V: 1310,3051 2896,3084
  rectangle net +24V: 1742,2267 1856,2613
  rectangle net +24V: 202,1583 466,1929
  rectangle net +24V: -65,1860 247,1934
  rectangle net +24V: 3150,100 3218,418
  rectangle net +24V: 2055,96 2132,413
  rectangle net +24V: 980,118 1033,400
  rectangle net +24V: 277,366 4758,427
  region net +24V: 407,1691 698,1691 759,1752 759,2426 988,2655 1835,2655 1960,2780 1960,3325 1989,3354 1992,3351 2201,3351 2245,3307 2245,2729 1841,2325 1797,2325 1737,2395 1737,2505 1732,2505 1695,2542 1088,2542 861,2315 861,1619 835,1593 437,1593 403,1627 403,1689

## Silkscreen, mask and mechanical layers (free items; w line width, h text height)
Top Overlay:
  lines w10: 500,435 625,435 ; 595,465 625,435 ; 600,410 625,435 ; 1395,2760 1520,2760 ; 1490,2790 1520,2760 ; 1495,2735 1520,2760 ; 1570,435 1695,435 ; 1665,465 1695,435 ; 1670,410 1695,435 ; 2645,2765 2770,2765 ; 2650,445 2775,445 ; 2740,2795 2770,2765 ; 2745,475 2775,445 ; 2745,2740 2770,2765 ; 2750,420 2775,445 ; -68,1693 -68,2575 -38,2605 686,2605 715,2576 715,2539 715,1693 692,1670 -45,1670 -68,1693 ; 795,1532 795,1774 814,1793 944,1793 959,1808 1189,1808 1204,1793 1334,1793 1364,1763 1364,1538 1339,1513 814,1513 795,1532
  text "RGB-LED" at 225,3400 h45 r270
  text "+5V" at -60,3075 h30
  text "PD11" at 4205,3010 h30 r270
  text "PD13" at 4270,3010 h30 r270
  text "PB14" at 4485,3010 h30 r270
  text "PE15" at 3995,3005 h30 r270
  text "PE14" at 4060,3005 h30 r270
  text "PD10" at 4400,3005 h30 r270
  text "5" at 3795,3000 h30 r270
  text "3.3" at 3885,3000 h30 r270
  text "GND" at 3270,2920 h45
  text "GND" at 3035,2910 h65
  text "PUL1+" at 4840,2905 h45
  text "GND" at 3795,2895 h30 r270
  text "PB12" at 3880,2895 h30 r270
  text "PD8" at 4060,2870 h30 r270
  text "PD12" at 4200,2870 h30 r270
  text "PB15" at 4395,2865 h30 r270
  text "PB13" at 4485,2865 h30 r270
  text "PB1" at 3990,2860 h30 r270
  text "PD9" at 4270,2840 h30 r270
  text "PUL1-" at 4840,2825 h45
  text "+24V" at 2125,2740 h45
  text "+24V" at 1865,2735 h65
  text "OUT8" at 2805,2720 h70
  text "OUT4" at 1555,2715 h70
  text "OUT5" at 2345,2715 h70
  text "OUT1" at 1095,2710 h70
  text "GND" at -35,2630 h45
  text "DIR1+" at 4835,2605 h45
  text "INC-MBTMC429-01" at 1665,2565 h70
  text "DIR1-" at 4835,2525 h45
  text "Power" at -26,2518 h45
  text "+3.3V" at 732,2493 h50
  text "20180503" at 1595,2445 h30
  text "PUL2+" at 4840,2210 h45
  text "PUL2-" at 4840,2130 h45
  text "GND" at 2430,2085 h30 r90
  text "+3.3V" at 2130,2025 h30 r90
  text "SWDIO" at 2335,2025 h30 r90
  text "SWCLK" at 2235,2020 h30 r90
  text "DIR2+" at 4830,1895 h45
  text "DIR2-" at 4830,1815 h45
  text "+5V" at 725,1800 h45
  text "EEPROM" at 979,1763 h30
  text "BOOT" at 1735,1715 h45
  text "PUL3+" at 4820,1520 h45
  text "RESET" at 1700,1485 h45
  text "24V" at 285,1470 h100
  text "PUL3-" at 4820,1440 h45
  text "0V" at 285,1265 h100
  text "DIR3+" at 4825,1205 h45
  text "DIR3-" at 4825,1125 h45
  text "GND" at 1165,380 h45
  text "GND" at 3280,380 h45
  text "GND" at 3430,380 h45
  text "L1" at 3750,380 h60
  text "L2" at 4140,380 h60
  text "R2" at 4345,380 h60
  text "IN4" at 630,375 h70
  text "IN12" at 2780,375 h70
  text "R1" at 3930,375 h60
  text "L3" at 4575,375 h60
  text "R3" at 4765,375 h60
  text "IN1" at 335,370 h70
  text "+24V" at 865,370 h65
  text "GND" at 2235,370 h45
  text "IN9" at 2470,370 h70
  text "+24V" at 3015,370 h65
  text "IN8" at 1700,365 h70
  text "IN5" at 1405,360 h70
  text "+24V" at 1935,360 h65
Mechanical 1:
  circle w3.94: c5281,3313 r68.9
  circle w3.94: c5,122 r68.9
  circle w3.94: c5,3314 r68.9
  lines w10: 5276,0 ccw(c5279.5,123.5) 5403,120 5403,3344 ccw(c5295,3342) 5293,3450 -2,3450 ccw(c0.5,3332.5) -117,3330 -117,120 ccw(c3,120) 3,0 5283,0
